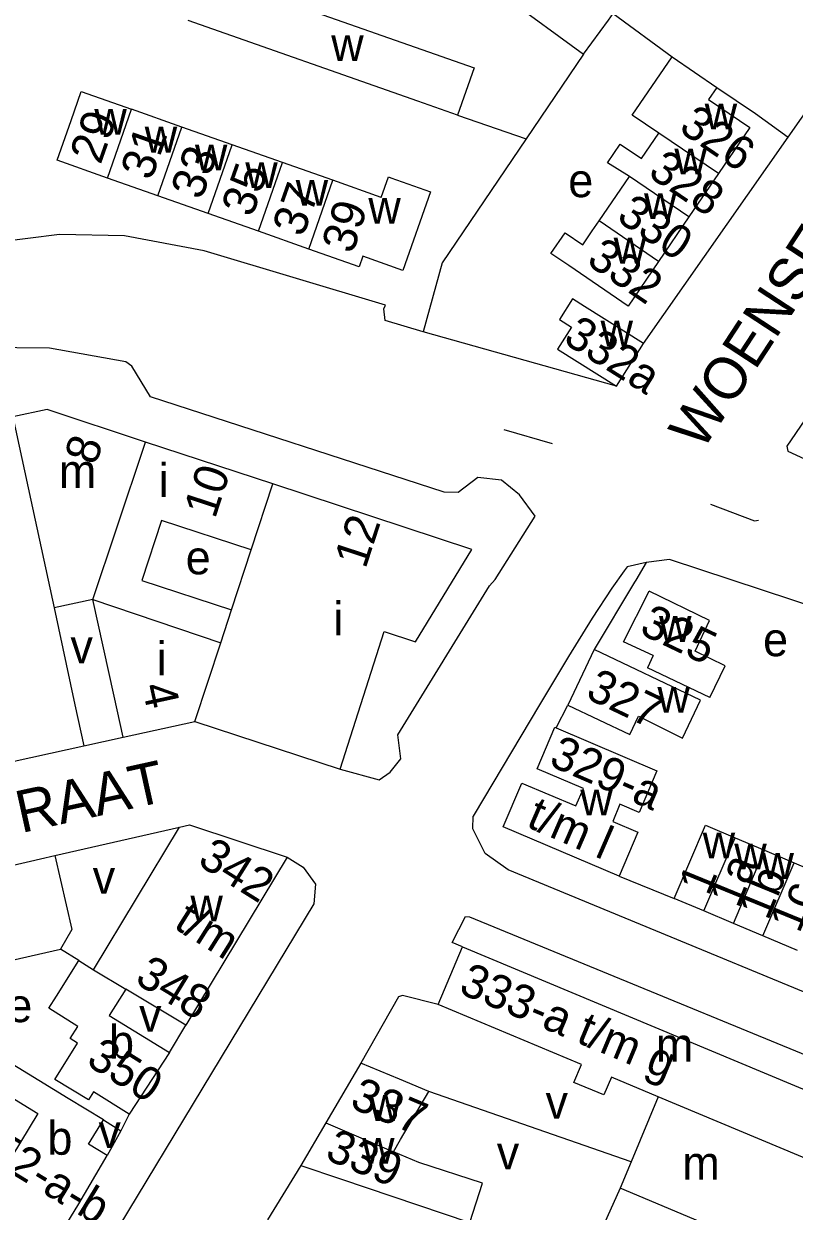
# Model space of a CAD drawing. Extents: x 159294 to 161936, y 384538 to 386517.
# Drawn here: x 160840.4 to 160932.2, y 385820.6 to 385962 of the extents above; entities that cross this region are included whole.
import ezdxf

# ---------------------------------------------------------------- set-up
doc = ezdxf.new("R2010")
doc.units = 0
for name, color, linetype in [('BLT_Basislijn', 7, 'Continuous'), ('BLT_Bebouwing', 7, 'Continuous'), ('BLT_Centroide', 7, 'Continuous'), ('BLT_Huisnummer', 7, 'Continuous'), ('BLT_Huisnummer_ tussenligend', 7, 'Continuous'), ('BLT_Huisnummer_reeks', 7, 'Continuous'), ('BLT_Onderdoorgang_en_onderverdeling', 7, 'Continuous'), ('BLT_Onderverdeling_panden', 7, 'Continuous'), ('BLT_Straatnaam', 7, 'Continuous')]:
    doc.layers.add(name, color=color, linetype=linetype)

msp = doc.modelspace()

# ---------------------------------------------------------------- linework, layer by layer
at = {"layer": 'BLT_Basislijn'}
for p, q in [((160907.08, 385958.42), (160900.23, 385948.32)), ((160892.07, 385951.15), (160900.23, 385948.32)), ((160914.19, 385923.95), (160931.43, 385948.53)), ((160910.99, 385918.87), (160887.99, 385925.36)), ((160897.58, 385913.74), (160903.34, 385912.07)), ((160903.82, 385878.19), (160905.18, 385880.92)), ((160847.59, 385876.06), (160852.25, 385877.08)), ((160911.32, 385860.54), (160917.87, 385857.89)), ((160892.65, 385852.13), (160891.43, 385852.64)), ((160846.97, 385850.51), (160844.8, 385851.87)), ((160857.78, 385839.54), (160859.73, 385842.79)), ((160912.74, 385826.52), (160888.64, 385834.92)), ((160849.91, 385831.53), (160851.97, 385830.23)), ((160852.97, 385832.19), (160851.97, 385830.23)), ((160851.97, 385830.23), (160850.36, 385827.27)), ((160873.41, 385826.08), (160869.46, 385819.62)), ((160911.43, 385823.38), (160907.58, 385814.83))]:
    msp.add_line(p, q, dxfattribs=at)
for points in [[(160931.43, 385948.53), (160943.58, 385965.85), (160943.74, 385970.38), (160940.73, 385973.98), (160926.85, 385985.57), (160902.43, 386003.18)], [(160910.6, 385963.24), (160917.6, 385958.08)], [(160922.94, 385954.45), (160927.53, 385951.35), (160931.43, 385948.53)], [(160900.23, 385948.32), (160890.22, 385933.57), (160887.99, 385925.36)], [(160887.99, 385925.36), (160883.44, 385926.7), (160883.29, 385928.09), (160883.51, 385928.54), (160861.9, 385934.99), (160852.41, 385936.78), (160844.7, 385936.94), (160837.12, 385935.98), (160790.19, 385925.81)], [(160878.09, 385873.27), (160882.75, 385872.03), (160884.03, 385872.93), (160885.3, 385874.52), (160884.95, 385877.35), (160895.88, 385895.1), (160896.53, 385895.86), (160901.29, 385903.4), (160899.44, 385905.93), (160897.31, 385907.67), (160894.48, 385908.01), (160892.15, 385906.21), (160890.48, 385906.26), (160855.53, 385917.61), (160853.29, 385921.28), (160852.6, 385921.78), (160843.49, 385923.4), (160835.67, 385923.48), (160835.16, 385923.35), (160832.82, 385920.7), (160749.73, 385901.19), (160744.7, 385901.94), (160733.87, 385898.4), (160732.63, 385897.5)], [(160935.05, 385917.27), (160931.27, 385911.75), (160931.39, 385911.14), (160955.66, 385899.97)], [(160922.2, 385904.82), (160927.4, 385902.86), (160927.9, 385902.91)], [(160914.51, 385897.89), (160912.27, 385897.36), (160911.92, 385896.9), (160910.43, 385894.82), (160908.08, 385891.26), (160905.27, 385886.71), (160901.82, 385880.95), (160894.06, 385867.88), (160893.94, 385867.68)], [(160914.51, 385897.89), (160913.29, 385895.8)], [(160944.15, 385889.4), (160942.94, 385889.8), (160917.31, 385898.24), (160914.51, 385897.89)], [(160913.29, 385895.8), (160913.14, 385895.54), (160908.34, 385887.54)], [(160898.11, 385861.3), (160895.37, 385863.23), (160893.88, 385866.18), (160893.94, 385867.68)], [(160844.14, 385862.99), (160858.98, 385866.38)], [(160871.78, 385862.82), (160873.71, 385861.61), (160875.18, 385859.61), (160874.95, 385857.23), (160838.41, 385796.78), (160835.65, 385796.65), (160832.57, 385797.73)], [(161023.53, 385863.24), (161041.99, 385857.23), (161044.22, 385855.09), (161044.48, 385854.08), (161044.54, 385851.52), (161033.39, 385818.69), (161032.05, 385817.03), (161029.79, 385815.44), (161025.75, 385815.17), (161017.84, 385817.45), (161004.84, 385821.93), (160952.66, 385838.75), (160898.11, 385861.3)], [(160891.43, 385852.64), (160893.03, 385855.76), (160893.51, 385855.69), (160949.5, 385832.7), (161020.6, 385810.15), (161024.24, 385808.52), (161025.12, 385807.33), (161025.04, 385804.37)], [(160889.77, 385845.25), (160885.53, 385846.33), (160885.05, 385846.19), (160880.55, 385838.28)]]:
    msp.add_lwpolyline(points, dxfattribs=at)
at = {"layer": 'BLT_Bebouwing'}
for p, q in [((160883.63, 385975.55), (160907.08, 385958.42)), ((160917.6, 385958.08), (160922.94, 385954.45)), ((160859.26, 385949.73), (160853.27, 385951.84)), ((160865.25, 385947.61), (160859.26, 385949.73)), ((160871.24, 385945.5), (160865.25, 385947.61)), ((160877.23, 385943.39), (160871.24, 385945.5)), ((160856.38, 385941.55), (160850.39, 385943.66)), ((160882.99, 385941.36), (160877.23, 385943.39)), ((160908.91, 385938.55), (160912.52, 385943.86)), ((160923.12, 385944.18), (160919.62, 385939.04)), ((160862.37, 385939.43), (160856.38, 385941.55)), ((160868.36, 385937.32), (160862.37, 385939.43)), ((160919.62, 385939.04), (160916.01, 385933.72)), ((160874.35, 385935.2), (160868.36, 385937.32)), ((160910.99, 385918.87), (160914.19, 385923.95)), ((160870.09, 385907.24), (160854.91, 385912.23)), ((160911.82, 385888.44), (160914.87, 385894.46)), ((160922.07, 385891), (160914.87, 385894.46)), ((160848.66, 385893.49), (160844.05, 385892.48)), ((160920.34, 385887.33), (160922.07, 385891)), ((160915.37, 385886.81), (160911.82, 385888.44)), ((160908.34, 385887.54), (160905.18, 385880.92)), ((160915.37, 385886.81), (160914.67, 385885.36)), ((160923.92, 385885.58), (160920.34, 385887.33)), ((160922.12, 385881.81), (160914.67, 385885.36)), ((160922.12, 385881.81), (160923.92, 385885.58)), ((160852.25, 385877.08), (160860.8, 385878.95)), ((160860.8, 385878.95), (160878.09, 385873.27)), ((160901.55, 385873.31), (160903.65, 385878.27)), ((160903.65, 385878.27), (160903.82, 385878.19)), ((160903.82, 385878.19), (160915.8, 385873.09)), ((160820.58, 385870.15), (160847.59, 385876.06)), ((160907.05, 385870.98), (160901.55, 385873.31)), ((160915.8, 385873.09), (160913.69, 385868.13)), ((160897.51, 385866.41), (160899.73, 385871.63)), ((160899.73, 385871.63), (160906.15, 385868.9)), ((160906.15, 385868.9), (160907.05, 385870.98)), ((160911.4, 385869.11), (160910.56, 385867.05)), ((160913.69, 385868.13), (160911.4, 385869.11)), ((160910.56, 385867.05), (160913.55, 385865.78)), ((160911.32, 385860.54), (160897.51, 385866.41)), ((160913.55, 385865.78), (160911.32, 385860.54)), ((160925.11, 385865.12), (160928.62, 385863.63)), ((160826.13, 385858.87), (160844.14, 385862.99)), ((160928.62, 385863.63), (160932.14, 385862.13)), ((160932.14, 385862.13), (160935.65, 385860.64)), ((160921.39, 385856.4), (160917.87, 385857.89)), ((160924.91, 385854.91), (160921.39, 385856.4)), ((160928.42, 385853.42), (160924.91, 385854.91)), ((160932.52, 385851.68), (160928.42, 385853.42)), ((160828.49, 385848.13), (160844.8, 385851.87)), ((160889.77, 385845.25), (160892.65, 385852.13)), ((160892.65, 385852.13), (160941.52, 385831.69)), ((160852.57, 385847.1), (160850.59, 385843.95)), ((160850.59, 385843.95), (160857.78, 385839.54)), ((160842.21, 385836.22), (160835.7, 385840.18)), ((160880.55, 385838.28), (160876.38, 385831.16)), ((160915.97, 385834.26), (160912.74, 385826.52)), ((160876.38, 385831.16), (160873.41, 385826.08)), ((160847, 385821.55), (160850.36, 385827.27)), ((160912.74, 385826.52), (160911.43, 385823.38)), ((160942.28, 385810.48), (160911.43, 385823.38))]:
    msp.add_line(p, q, dxfattribs=at)
for points in [[(160861.99, 385968.05), (160894.05, 385956.77), (160892.07, 385951.15)], [(160907.08, 385958.42), (160910.03, 385962.45), (160910.6, 385963.24)], [(160892.07, 385951.15), (160887.35, 385952.8), (160860.01, 385962.42)], [(160916.02, 385949), (160912.87, 385951.13), (160917.6, 385958.08)], [(160922.94, 385954.45), (160921.95, 385953), (160926.85, 385949.67), (160923.12, 385944.18)], [(160850.39, 385943.66), (160844.4, 385945.77), (160846.06, 385950.49), (160847.28, 385953.96), (160853.27, 385951.84)], [(160912.52, 385943.86), (160909.92, 385945.48), (160911.44, 385947.71), (160913.97, 385945.99), (160916.02, 385949)], [(160882.99, 385941.36), (160883.84, 385943.79), (160884.13, 385943.68), (160888.84, 385942.02), (160885.54, 385932.67), (160880.78, 385934.35)], [(160916.01, 385933.72), (160912.4, 385928.4), (160905.3, 385933.23), (160903.19, 385934.66), (160904.88, 385937.15), (160906.99, 385935.72), (160908.11, 385937.36), (160908.91, 385938.55)], [(160880.78, 385934.35), (160880.34, 385933.09), (160874.35, 385935.2)], [(160914.19, 385923.95), (160907.17, 385928.37), (160905.76, 385929.26), (160904.21, 385926.8), (160905.63, 385925.91), (160903.98, 385923.29), (160910.99, 385918.87)], [(160854.91, 385912.23), (160843.2, 385916.09), (160839.15, 385915.21)], [(160878.09, 385873.27), (160883.34, 385889.66), (160887.08, 385888.43), (160893.77, 385899.44), (160870.09, 385907.24)], [(160867.49, 385899.38), (160856.82, 385902.88), (160854.48, 385895.75), (160865.16, 385892.26)], [(160865.16, 385892.26), (160867.49, 385899.38)], [(160844.05, 385892.48), (160846.52, 385880.94), (160847.59, 385876.06)], [(160852.25, 385877.08), (160851.18, 385881.96), (160848.66, 385893.49)], [(160921.01, 385881.49), (160908.34, 385887.54)], [(160905.18, 385880.92), (160912.57, 385877.39), (160913.63, 385879.6), (160918.86, 385876.98), (160921.01, 385881.49)], [(160848.75, 385849.39), (160858.98, 385866.38)], [(160858.98, 385866.38), (160860.16, 385866.66), (160871.78, 385862.82)], [(160917.87, 385857.89), (160921.59, 385866.62), (160925.11, 385865.12)], [(160844.14, 385862.99), (160846.17, 385854.18)], [(160871.78, 385862.82), (160859.73, 385842.79)], [(160846.17, 385854.18), (160844.8, 385851.87)], [(160852.97, 385832.19), (160848.74, 385834.85), (160848.14, 385833.91), (160844.13, 385836.34), (160846.84, 385840.66), (160845.97, 385841.21), (160846.88, 385842.65), (160843.41, 385844.83), (160844.31, 385846.27), (160846.97, 385850.51)], [(160846.97, 385850.51), (160848.75, 385849.39)], [(160859.73, 385842.79), (160852.57, 385847.1)], [(160915.97, 385834.26), (160910.38, 385836.6), (160909.5, 385834.5), (160905.92, 385835.99), (160906.81, 385838.13), (160889.77, 385845.25)], [(160857.78, 385839.54), (160852.97, 385832.19)], [(160833.93, 385837.28), (160842.12, 385832.29), (160836.92, 385823.77), (160828.74, 385828.76)], [(160888.64, 385834.92), (160885.17, 385836.36), (160880.55, 385838.28)], [(160849.91, 385831.53), (160845.73, 385834.08), (160842.21, 385836.22)], [(160884.44, 385827.74), (160885.26, 385829.18), (160888.64, 385834.92)], [(160850.36, 385827.27), (160848.14, 385828.62), (160849.91, 385831.53)], [(160893.55, 385819.32), (160895.04, 385824), (160887.47, 385826.44), (160884.44, 385827.74)], [(160873.41, 385826.08), (160878.15, 385824.49), (160893.55, 385819.32)], [(160840.86, 385814.11), (160842.42, 385816.67), (160843.59, 385815.95), (160847, 385821.55)]]:
    msp.add_lwpolyline(points, dxfattribs=at)
at = {"layer": 'BLT_Onderdoorgang_en_onderverdeling'}
msp.add_line((160938.63, 385824.78), (160915.97, 385834.26), dxfattribs=at)
at = {"layer": 'BLT_Onderverdeling_panden'}
for p, q in [((160850.39, 385943.66), (160853.27, 385951.84)), ((160856.38, 385941.55), (160859.26, 385949.73)), ((160923.12, 385944.18), (160916.02, 385949)), ((160862.37, 385939.43), (160865.25, 385947.61)), ((160868.36, 385937.32), (160871.24, 385945.5)), ((160874.35, 385935.2), (160877.23, 385943.39)), ((160919.62, 385939.04), (160912.52, 385943.86)), ((160916.01, 385933.72), (160908.91, 385938.55)), ((160848.66, 385893.49), (160863.88, 385888.32)), ((160860.8, 385878.95), (160863.88, 385888.32)), ((160921.39, 385856.4), (160925.11, 385865.12)), ((160924.91, 385854.91), (160928.62, 385863.63)), ((160928.42, 385853.42), (160932.14, 385862.13)), ((160848.75, 385849.39), (160852.57, 385847.1))]:
    msp.add_line(p, q, dxfattribs=at)
for points in [[(160839.15, 385915.21), (160841.29, 385905.3)], [(160848.66, 385893.49), (160851.47, 385901.91), (160854.91, 385912.23)], [(160867.49, 385899.38), (160870.09, 385907.24)], [(160841.29, 385905.3), (160844.05, 385892.48)], [(160863.88, 385888.32), (160865.16, 385892.26)], [(160876.38, 385831.16), (160884.44, 385827.74)]]:
    msp.add_lwpolyline(points, dxfattribs=at)

# ---------------------------------------------------------------- texts
at = {"layer": 'BLT_Centroide'}
for s, p in [('w', (160877.03, 385957.59)), ('w', (160848.83, 385948.81)), ('w', (160921.49, 385949.44)), ('w', (160854.83, 385946.69)), ('w', (160860.81, 385944.58)), ('w', (160917.88, 385944.09)), ('w', (160866.8, 385942.47)), ('e', (160905.25, 385941.38)), ('w', (160872.8, 385940.36)), ('w', (160914.27, 385938.78)), ('w', (160881.45, 385938.22)), ('w', (160910.66, 385933.47)), ('w', (160909.09, 385923.62)), ('m', (160844.61, 385906.76)), ('i', (160856.5, 385905.69)), ('e', (160859.71, 385896.48)), ('i', (160877.28, 385889.2)), ('w', (160916.05, 385888.44)), ('e', (160928.44, 385886.73)), ('v', (160845.99, 385885.9)), ('i', (160856.27, 385884.44)), ('w', (160915.86, 385880.01)), ('w', (160906.68, 385867.77)), ('w', (160921.25, 385862.66)), ('w', (160925.01, 385861.34)), ('w', (160928.24, 385860.21)), ('v', (160848.64, 385858.44)), ('w', (160860.27, 385855.16)), ('e', (160838.47, 385843.16)), ('v', (160854.16, 385842.03)), ('b', (160850.59, 385838.81)), ('m', (160915.68, 385838.47)), ('w', (160881.53, 385831.41)), ('v', (160902.54, 385831.66)), ('b', (160843.25, 385827.38)), ('v', (160849.33, 385828.18)), ('w', (160880.7, 385826.31)), ('v', (160896.74, 385825.64)), ('m', (160918.83, 385824.39))]:
    msp.add_text(s, height=4, dxfattribs=at).set_placement(p)
at = {"layer": 'BLT_Huisnummer'}
for s, rotation, p in [('29', 70.5585, (160849.57, 385945.16)), ('326', 325.8006, (160918.26, 385949.31)), ('33', 70.5625, (160861.59, 385940.94)), ('39', 72.5218, (160879.61, 385934.52)), ('332', 325.7989, (160907.27, 385933.5)), ('332a', 327.8108, (160904.5, 385924.13)), ('8', 71.8749, (160848.99, 385909.35)), ('10', 71.831, (160863.19, 385902.99)), ('12', 71.831, (160881.1, 385897.03)), ('325', 334.4788, (160913.57, 385889.48)), ('327', 334.4791, (160907.16, 385881.82)), ('4', 282.3366, (160854.49, 385883.16)), ('1a', 67.7319, (160925.53, 385856.6)), ('1', 67.7319, (160921.95, 385858.07)), ('1b', 67.7319, (160929.03, 385855.16)), ('1c', 67.7319, (160932.75, 385853.63)), ('350', 327.861, (160847.71, 385838.18)), ('337', 337.0534, (160879.1, 385833.06)), ('339', 337.0534, (160876.14, 385826.93))]:
    msp.add_text(s, height=4, rotation=rotation, dxfattribs=at).set_placement(p)
at = {"layer": 'BLT_Huisnummer_ tussenligend'}
for s, rotation, p in [('31', 70.5585, (160855.61, 385943.25)), ('328', 325.8006, (160914.59, 385943.96)), ('35', 70.5625, (160867.61, 385938.87)), ('37', 70.5625, (160873.68, 385936.52)), ('330', 325.8006, (160910.84, 385938.69))]:
    msp.add_text(s, height=4, rotation=rotation, dxfattribs=at).set_placement(p)
at = {"layer": 'BLT_Huisnummer_reeks'}
for s, rotation, p in [('329-a', 336.4791, (160902.8, 385873.78)), ('t/m l', 336.4791, (160900.11, 385866.49)), ('342', 327.8806, (160860.97, 385861.99)), ('t/m', 327.8257, (160858.13, 385854.46)), ('348', 328.6724, (160853.5, 385847.92)), ('333-a t/m g', 337.3048, (160892.06, 385846.68)), ('352-a-b', 328.6724, (160833.36, 385828.5))]:
    msp.add_text(s, height=4, rotation=rotation, dxfattribs=at).set_placement(p)
at = {"layer": 'BLT_Straatnaam'}
for s, rotation, p in [('WOENSELSESTRAAT', 56.7863, (160921.17, 385911.03)), ('HANARTSTRAAT', 12.4395, (160804.93, 385857.9))]:
    msp.add_text(s, height=5, rotation=rotation, dxfattribs=at).set_placement(p)

doc.saveas('drawing.dxf')
